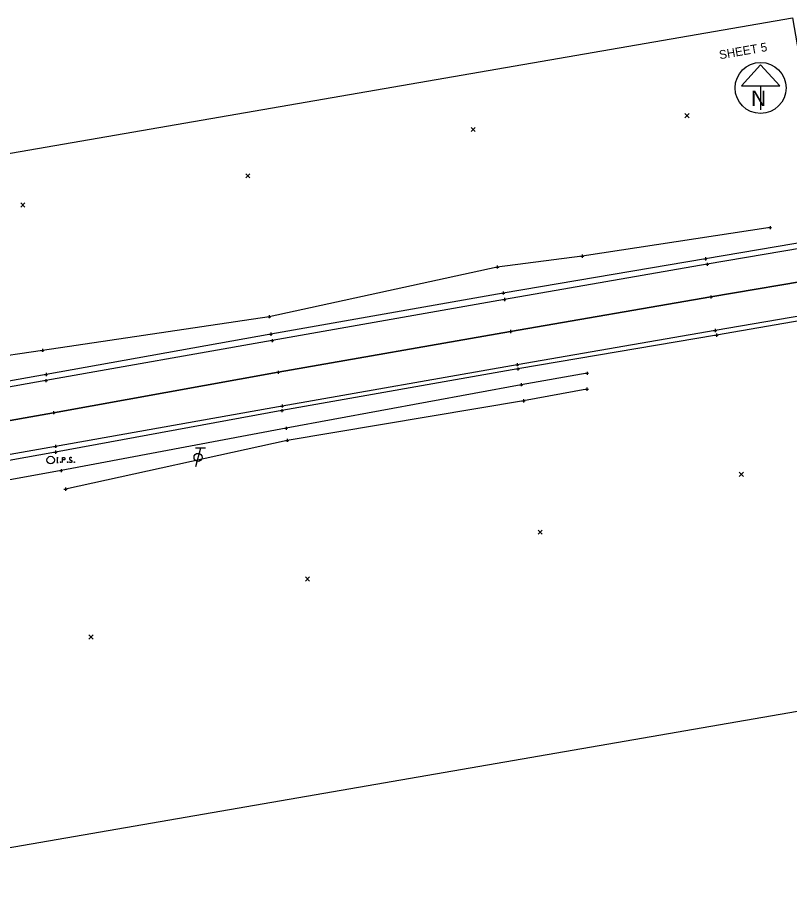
# Model space of a CAD drawing. Extents: x 1386013 to 1389776, y 604170 to 607009.
# Drawn here: x 1387776 to 1388024, y 604719.4 to 605004.7 of the extents above; entities that cross this region are included whole.
import ezdxf

# ---------------------------------------------------------------- set-up
doc = ezdxf.new("R2010")
doc.units = 0
for name, color, linetype in [('DV_X_Text', 7, 'Continuous'), ('PM_X_CL_Double_Solid', 7, 'Continuous'), ('PV_X_COP', 7, 'Continuous'), ('PV_X_EOP', 7, 'Continuous'), ('PV_X_Shoulder', 7, 'Continuous'), ('SC_Scratch13', 7, 'Continuous'), ('SH_Cut_Line', 7, 'Continuous'), ('SH_Masking', 7, 'Continuous'), ('SH_Text', 7, 'Continuous'), ('SV_X_Random_Point', 7, 'Continuous'), ('SV_X_Toe_of_Slope', 7, 'Continuous'), ('SV_X_Top_of_Bank', 7, 'Continuous'), ('UT_X_Telecom_Cells', 7, 'Continuous')]:
    doc.layers.add(name, color=color, linetype=linetype)

msp = doc.modelspace()

# ---------------------------------------------------------------- linework, layer by layer
at = {"layer": 'DV_X_Text'}
for p, q in [((1388017.36, 604937.27), (1388018.36, 604937.27)), ((1388017.86, 604937.77), (1388017.86, 604936.77)), ((1388017.86, 604937.27), (1388017.86, 604937.27)), ((1387956.98, 604928.09), (1387957.98, 604928.09)), ((1387957.48, 604928.59), (1387957.48, 604927.59)), ((1387957.48, 604928.09), (1387957.48, 604928.09)), ((1387996.58, 604927.24), (1387997.58, 604927.24)), ((1387997.08, 604927.74), (1387997.08, 604926.74)), ((1387997.08, 604927.24), (1387997.08, 604927.24)), ((1387929.69, 604924.57), (1387930.69, 604924.57)), ((1387930.19, 604925.07), (1387930.19, 604924.07)), ((1387930.19, 604924.57), (1387930.19, 604924.57)), ((1387997.17, 604925.46), (1387998.17, 604925.46)), ((1387997.67, 604925.96), (1387997.67, 604924.96)), ((1387997.67, 604925.46), (1387997.67, 604925.46)), ((1387931.6, 604916.23), (1387932.6, 604916.23)), ((1387932.1, 604916.73), (1387932.1, 604915.73)), ((1387932.1, 604916.23), (1387932.1, 604916.23)), ((1387998.85, 604915.47), (1387998.85, 604914.47)), ((1387931.95, 604914.15), (1387932.95, 604914.15)), ((1387932.45, 604914.65), (1387932.45, 604913.65)), ((1387932.45, 604914.15), (1387932.45, 604914.15)), ((1387998.35, 604914.97), (1387999.35, 604914.97)), ((1387998.85, 604914.97), (1387998.85, 604914.97)), ((1387856.39, 604908.62), (1387857.39, 604908.62)), ((1387856.89, 604909.12), (1387856.89, 604908.12)), ((1387856.89, 604908.62), (1387856.89, 604908.62)), ((1387934.47, 604904.36), (1387934.47, 604903.36)), ((1387999.7, 604904.18), (1388000.7, 604904.18)), ((1388000.2, 604904.68), (1388000.2, 604903.68)), ((1388000.2, 604904.18), (1388000.2, 604904.18)), ((1387856.84, 604902.99), (1387857.84, 604902.99)), ((1387857.34, 604903.49), (1387857.34, 604902.49)), ((1387857.34, 604902.99), (1387857.34, 604902.99)), ((1387857.85, 604901.42), (1387857.85, 604900.42)), ((1387933.97, 604903.86), (1387934.97, 604903.86)), ((1387934.47, 604903.86), (1387934.47, 604903.86)), ((1388000.13, 604902.69), (1388001.13, 604902.69)), ((1388000.63, 604903.19), (1388000.63, 604902.19)), ((1388000.63, 604902.69), (1388000.63, 604902.69)), ((1387783.98, 604898.28), (1387783.98, 604897.28)), ((1387857.35, 604900.92), (1387858.35, 604900.92)), ((1387857.85, 604900.92), (1387857.85, 604900.92)), ((1387783.48, 604897.78), (1387784.48, 604897.78)), ((1387783.98, 604897.78), (1387783.98, 604897.78)), ((1387936.11, 604893.17), (1387937.11, 604893.17)), ((1387936.61, 604893.67), (1387936.61, 604892.67)), ((1387936.61, 604893.17), (1387936.61, 604893.17)), ((1387784.66, 604890.04), (1387785.66, 604890.04)), ((1387785.16, 604890.54), (1387785.16, 604889.54)), ((1387785.16, 604890.04), (1387785.16, 604890.04)), ((1387859.23, 604890.76), (1387860.23, 604890.76)), ((1387859.73, 604891.26), (1387859.73, 604890.26)), ((1387859.73, 604890.76), (1387859.73, 604890.76)), ((1387936.29, 604891.84), (1387937.29, 604891.84)), ((1387936.79, 604892.34), (1387936.79, 604891.34)), ((1387936.79, 604891.84), (1387936.79, 604891.84)), ((1387958.53, 604890.44), (1387959.53, 604890.44)), ((1387959.03, 604890.94), (1387959.03, 604889.94)), ((1387959.03, 604890.44), (1387959.03, 604890.44)), ((1387784.6, 604888.09), (1387785.6, 604888.09)), ((1387785.1, 604888.59), (1387785.1, 604887.59)), ((1387785.1, 604888.09), (1387785.1, 604888.09)), ((1387937.87, 604887.26), (1387937.87, 604886.26)), ((1387937.37, 604886.76), (1387938.37, 604886.76)), ((1387937.87, 604886.76), (1387937.87, 604886.76)), ((1387958.48, 604885.33), (1387959.48, 604885.33)), ((1387958.98, 604885.83), (1387958.98, 604884.83)), ((1387958.98, 604885.33), (1387958.98, 604885.33)), ((1387938.11, 604881.58), (1387939.11, 604881.58)), ((1387938.61, 604882.08), (1387938.61, 604881.08)), ((1387938.61, 604881.58), (1387938.61, 604881.58)), ((1387860.48, 604878.42), (1387861.48, 604878.42)), ((1387860.5, 604879.89), (1387861.5, 604879.89)), ((1387860.98, 604878.92), (1387860.98, 604877.92)), ((1387860.98, 604878.42), (1387860.98, 604878.42)), ((1387861, 604880.39), (1387861, 604879.39)), ((1387861, 604879.89), (1387861, 604879.89)), ((1387787, 604877.74), (1387788, 604877.74)), ((1387787.5, 604878.24), (1387787.5, 604877.24)), ((1387787.5, 604877.74), (1387787.5, 604877.74)), ((1387861.8, 604872.74), (1387862.8, 604872.74)), ((1387862.3, 604873.24), (1387862.3, 604872.24)), ((1387862.3, 604872.74), (1387862.3, 604872.74)), ((1387787.65, 604866.91), (1387788.65, 604866.91)), ((1387788.15, 604867.41), (1387788.15, 604866.41)), ((1387788.15, 604866.91), (1387788.15, 604866.91)), ((1387862.16, 604868.86), (1387863.16, 604868.86)), ((1387862.66, 604869.36), (1387862.66, 604868.36)), ((1387862.66, 604868.86), (1387862.66, 604868.86)), ((1387787.69, 604865.06), (1387788.69, 604865.06)), ((1387788.19, 604865.56), (1387788.19, 604864.56)), ((1387788.19, 604865.06), (1387788.19, 604865.06)), ((1387789.45, 604859.14), (1387790.45, 604859.14)), ((1387789.95, 604859.64), (1387789.95, 604858.64)), ((1387789.95, 604859.14), (1387789.95, 604859.14)), ((1387790.9, 604853.19), (1387791.9, 604853.19)), ((1387791.4, 604853.69), (1387791.4, 604852.69)), ((1387791.4, 604853.19), (1387791.4, 604853.19))]:
    msp.add_line(p, q, dxfattribs=at)
at = {"layer": 'PM_X_CL_Double_Solid'}
msp.add_lwpolyline([(1386941.92, 604730.57), (1387000.37, 604739.9), (1387059.38, 604750.41), (1387127.32, 604761.93), (1387175.52, 604769.9), (1387233.31, 604779.13), (1387291.85, 604789.88), (1387343.04, 604798.39), (1387403.9, 604809.05), (1387458.49, 604818.93), (1387516.12, 604829.58), (1387574.82, 604839.73), (1387636.99, 604851.11), (1387704.35, 604863.01), (1387787.5, 604877.74), (1387859.73, 604890.76), (1387934.47, 604903.86), (1387998.85, 604914.97), (1388072.27, 604927.44)], dxfattribs=at)
at = {"layer": 'PV_X_COP'}
msp.add_lwpolyline([(1388072.27, 604927.44), (1387998.85, 604914.97), (1387934.47, 604903.86), (1387859.73, 604890.76), (1387787.5, 604877.74), (1387704.35, 604863.01), (1387636.99, 604851.11), (1387574.82, 604839.73), (1387516.12, 604829.58), (1387458.49, 604818.93), (1387403.9, 604809.05), (1387343.04, 604798.39), (1387291.85, 604789.88), (1387233.31, 604779.13), (1387175.52, 604769.9), (1387127.32, 604761.93), (1387059.38, 604750.41), (1387000.37, 604739.9), (1386941.92, 604730.57)], dxfattribs=at)
at = {"layer": 'PV_X_EOP'}
for points in [[(1388070.9, 604937.92), (1387997.67, 604925.46), (1387932.45, 604914.15), (1387857.85, 604900.92), (1387785.1, 604888.09), (1387704.04, 604873.65), (1387634.94, 604861.37), (1387573.23, 604850.33), (1387514.48, 604840.1), (1387457.17, 604829.65), (1387402.44, 604819.9), (1387341.38, 604808.9), (1387290.36, 604800.04), (1387231.98, 604789.91), (1387174.35, 604780.15), (1387125.76, 604771.91), (1387057.82, 604760.3), (1386999.09, 604750.97), (1386941.41, 604741.04)], [(1388073.48, 604916.74), (1388000.2, 604904.18), (1387936.61, 604893.17), (1387861, 604879.89), (1387788.15, 604866.91), (1387706.18, 604852.38), (1387637.62, 604840.16), (1387577.04, 604829.26), (1387518.08, 604818.58), (1387459.96, 604808.24), (1387405.36, 604798.5), (1387345.11, 604787.75), (1387291.8, 604778.43), (1387234.86, 604768.47), (1387177.43, 604758.7), (1387129.4, 604750.56), (1387061.72, 604739.2), (1387002.9, 604729.17), (1386943.42, 604719.4)]]:
    msp.add_lwpolyline(points, dxfattribs=at)
at = {"layer": 'PV_X_Shoulder'}
for points in [[(1388070.88, 604939.75), (1387997.08, 604927.24), (1387932.1, 604916.23), (1387857.34, 604902.99), (1387785.16, 604890.04), (1387703.39, 604875.43), (1387634.35, 604863.66), (1387572.42, 604852.64), (1387514.1, 604842.11), (1387456.78, 604832.26), (1387401.91, 604822.43), (1387340.63, 604811.34), (1387290.11, 604802.67), (1387231.45, 604791.93), (1387174.18, 604782.71), (1387125.33, 604774.1), (1387057.54, 604762.26), (1386998.59, 604752.7), (1386940.97, 604743.32)], [(1388073.66, 604915.38), (1388000.63, 604902.69), (1387936.79, 604891.84), (1387860.98, 604878.42), (1387788.19, 604865.06), (1387706.38, 604850.4), (1387637.88, 604838.5), (1387577.02, 604827.53), (1387518.12, 604817.16), (1387460.26, 604806.85), (1387405.51, 604796.97), (1387345.32, 604786.5), (1387292.14, 604776.93), (1387235.04, 604767.03), (1387177.5, 604757.13), (1387129.28, 604748.59), (1387117.65, 604744.89), (1387099.29, 604741.91), (1387094.7, 604743.05), (1387062.03, 604737.87), (1387002.75, 604727.47), (1386990.61, 604725.25), (1386985.4, 604722.84), (1386965.11, 604719.46)]]:
    msp.add_lwpolyline(points, dxfattribs=at)
at = {"layer": 'SC_Scratch13'}
for points in [[(1387788.64, 604863.34), (1387788.99, 604863.34)], [(1387788.64, 604861.74), (1387788.99, 604861.74)], [(1387788.81, 604861.74), (1387788.81, 604863.34)], [(1387789.77, 604861.96), (1387789.83, 604861.96), (1387789.86, 604861.93), (1387789.89, 604861.88), (1387789.89, 604861.82), (1387789.86, 604861.77), (1387789.83, 604861.74), (1387789.77, 604861.74), (1387789.74, 604861.77), (1387789.71, 604861.82), (1387789.71, 604861.88), (1387789.74, 604861.93), (1387789.77, 604861.96)], [(1387790.38, 604861.74), (1387790.38, 604863.34), (1387790.91, 604863.34), (1387790.96, 604863.33), (1387791.04, 604863.31), (1387791.07, 604863.28), (1387791.11, 604863.26), (1387791.15, 604863.19), (1387791.18, 604863.13), (1387791.21, 604863.03), (1387791.21, 604862.88), (1387791.19, 604862.83), (1387791.17, 604862.75), (1387791.13, 604862.66), (1387791.08, 604862.63), (1387791.05, 604862.6), (1387791, 604862.58), (1387790.91, 604862.56), (1387790.38, 604862.56)], [(1387792.02, 604861.96), (1387792.08, 604861.96), (1387792.11, 604861.93), (1387792.14, 604861.88), (1387792.14, 604861.82), (1387792.11, 604861.77), (1387792.08, 604861.74), (1387792.02, 604861.74), (1387791.99, 604861.77), (1387791.95, 604861.82), (1387791.95, 604861.88), (1387791.99, 604861.93), (1387792.02, 604861.96)], [(1387793.39, 604863.23), (1387793.37, 604863.26), (1387793.33, 604863.28), (1387793.23, 604863.32), (1387793.11, 604863.34), (1387793.02, 604863.34), (1387792.99, 604863.34), (1387792.85, 604863.31), (1387792.73, 604863.23), (1387792.65, 604863.13), (1387792.63, 604863.03), (1387792.63, 604862.95), (1387792.65, 604862.85), (1387792.74, 604862.76), (1387793.34, 604862.39), (1387793.4, 604862.34), (1387793.42, 604862.29), (1387793.44, 604862.21), (1387793.44, 604862.13), (1387793.43, 604862.06), (1387793.42, 604862.01), (1387793.4, 604861.95), (1387793.38, 604861.9), (1387793.35, 604861.86), (1387793.32, 604861.82), (1387793.29, 604861.79), (1387793.24, 604861.77), (1387793.21, 604861.76), (1387793.11, 604861.74), (1387792.96, 604861.74), (1387792.86, 604861.77), (1387792.72, 604861.86), (1387792.63, 604861.93)], [(1387794.2, 604861.96), (1387794.26, 604861.96), (1387794.29, 604861.93), (1387794.32, 604861.88), (1387794.32, 604861.82), (1387794.29, 604861.77), (1387794.26, 604861.74), (1387794.2, 604861.74), (1387794.17, 604861.77), (1387794.14, 604861.82), (1387794.14, 604861.88), (1387794.17, 604861.93), (1387794.2, 604861.96)]]:
    msp.add_lwpolyline(points, dxfattribs=at)
msp.add_circle((1387786.62, 604862.54), 1.2, dxfattribs=at)
at = {"layer": 'SH_Cut_Line'}
msp.add_lwpolyline([(1387727.6, 604729.92), (1387690.05, 604946.7), (1388025.06, 605004.73), (1388062.61, 604787.96)], close=True, dxfattribs=at)
at = {"layer": 'SH_Masking'}
msp.add_circle((1388014.8, 604982.16), 8.2, dxfattribs=at)
at = {"layer": 'SH_Text'}
for p, q in [((1388014.8, 604989.64), (1388008.64, 604982.81)), ((1388020.95, 604982.81), (1388014.8, 604989.64)), ((1388008.64, 604982.81), (1388020.95, 604982.81)), ((1388014.8, 604982.81), (1388014.8, 604975.08))]:
    msp.add_line(p, q, dxfattribs=at)
msp.add_circle((1388014.8, 604982.16), 8.2, dxfattribs=at)
at = {"layer": 'SV_X_Random_Point'}
for p, q in [((1387990.49, 604972.58), (1387991.83, 604973.91)), ((1387990.49, 604973.91), (1387991.83, 604972.58)), ((1387921.78, 604968.12), (1387923.12, 604969.46)), ((1387921.78, 604969.46), (1387923.12, 604968.12)), ((1387849.31, 604953.24), (1387850.64, 604954.57)), ((1387849.31, 604954.57), (1387850.64, 604953.24)), ((1387777.02, 604943.85), (1387778.35, 604945.19)), ((1387777.02, 604945.19), (1387778.35, 604943.85)), ((1388007.96, 604857.27), (1388009.29, 604858.61)), ((1388007.96, 604858.61), (1388009.29, 604857.27)), ((1387943.33, 604838.67), (1387944.66, 604840)), ((1387943.33, 604840), (1387944.66, 604838.67)), ((1387868.49, 604823.62), (1387869.82, 604824.95)), ((1387868.49, 604824.95), (1387869.82, 604823.62)), ((1387798.92, 604804.98), (1387800.25, 604806.31)), ((1387798.92, 604806.31), (1387800.25, 604804.98))]:
    msp.add_line(p, q, dxfattribs=at)
at = {"layer": 'SV_X_Toe_of_Slope'}
for points in [[(1388017.86, 604937.27), (1387957.48, 604928.09), (1387930.19, 604924.57), (1387856.89, 604908.62), (1387783.98, 604897.78), (1387708, 604886.6)], [(1387959.03, 604890.44), (1387937.87, 604886.76), (1387862.3, 604872.74), (1387789.95, 604859.14), (1387705.64, 604843.8), (1387667.16, 604832.89)]]:
    msp.add_lwpolyline(points, dxfattribs=at)
at = {"layer": 'SV_X_Top_of_Bank'}
msp.add_lwpolyline([(1387958.98, 604885.33), (1387938.61, 604881.58), (1387862.66, 604868.86), (1387791.4, 604853.19)], dxfattribs=at)
at = {"layer": 'UT_X_Telecom_Cells'}
for p, q in [((1387834.81, 604866.39), (1387833.2, 604860.39)), ((1387836.41, 604866.39), (1387833.21, 604866.39))]:
    msp.add_line(p, q, dxfattribs=at)
msp.add_circle((1387834, 604863.39), 1.3, dxfattribs=at)

# ---------------------------------------------------------------- texts
at = {"layer": 'SH_Text'}
msp.add_text('SHEET 5', height=2.8, rotation=9.8279, dxfattribs=at).set_placement((1388001.75, 604991.37))
msp.add_text('N', height=5, dxfattribs=at).set_placement((1388011.77, 604976.34))

doc.saveas('drawing.dxf')
